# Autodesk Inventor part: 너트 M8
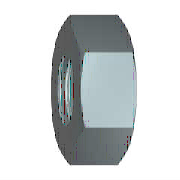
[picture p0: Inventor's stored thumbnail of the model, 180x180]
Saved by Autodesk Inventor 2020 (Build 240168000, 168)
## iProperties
Created: 2012-02
Part Number: 너트 M8
Material: 강철, 연강
Description: 6각 너트 및 6각 가는 너트
Document SubType Name: Modeling
Standard: KS B 1012
Designer: mduedu
Standards Organization: KS
Language: ko-KR
Size Designation: M 8
Categories: <MemberInstance><Categories><Category DisplayName="조임쇠" InternalName="e4da775c-781d-43d5-af7c-5136215cf5a6" Mnemonic="FSTN"><Category DisplayName="너트" InternalN
Density: 7.86 g/cm^3
Mass: 4.30432 g
Surface Area: 5.27675 cm^2
Volume: 0.547623 cm^3
Appearance: 강철
IsCustomPart: 1
Author: mduedu
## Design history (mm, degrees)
sketch "스케치1"
  geometry: L1 (-7.506, 0)-(-3.753, 6.5); L2 (-3.753, 6.5)-(3.753, 6.5); L3 (3.753, 6.5)-(7.506, 0); L4 (7.506, 0)-(3.753, -6.5); L5 (3.753, -6.5)-(-3.753, -6.5); L6 (-3.753, -6.5)-(-7.506, 0); 2 further points
  constraints: 12 end point, 1 coincident, 1 horizontal, 11 other
  dimensions: "d0" = 15.01111 distance of L3.end L1.start (= 1.1547 x SW)
extrude "본체" new body sketch "스케치1" distance "d1" = 5 (= KOH); taper "d2" = 0 deg
sketch "스케치2"
  geometry: L1 (0, 3.753)-(0, 7.506) reference; L2 (0, 7.506)-(5, 7.506) reference; L3 (5, 3.753)-(5, 7.506) reference; L4 (-1, 0)-(6, 0) reference; L5 (0.581, 7.506)-(0, 6.5); L6 (4.419, 7.506)-(5, 6.5)
  constraints: 4 end point, 4 point on line
  dimensions: "d3" = 30 deg angle of L1 L5 (= ANG1); "d4" = 30 deg angle of L3 L6 (= ANG2); "d5" = 13 diameter of L5.end L4 (= SW0); "d6" = 13 diameter of L6.end L4 (= SW01)
revolve "모따기1" sketch "스케치2" stored, may be unused: angle "d7" = 90 deg
sketch "스케치3"
  geometry: A1 r 6.5 centre (0, 0) between (-3.25, -5.629) and (3.25, -5.629) reference; 1 further point
  constraints: 1 coincident
hole "스레드" sketch "스케치3" at (0, 0) diameter "d25" = 6.647; stored, may be unused: countersink angle "d29" = 82 deg, drill point angle "d31" = 118 deg; dims "d26" = 6, "d27" = 4, "d28" = 2, "d30" = 8
workaxis "Work Axis1"
workplane "Work Plane1"
body "Solid1"
chamfer "모따기2" distance "d8" = 0.67658 (= -0.5 x GD1 + 0.5 x NND); stored, may be unused: angle "d9" = 30 deg, second distance "d40" = 0.67658 (= -0.5 x GD1 + 0.5 x NND)
chamfer "모따기3" distance "d10" = 0.67658 (= -0.5 x GD1 + 0.5 x NND); stored, may be unused: angle "d11" = 30 deg, second distance "d41" = 0.67658 (= -0.5 x GD1 + 0.5 x NND)
other parameters: "ANG1" = 30 deg [user parameter; used in 1 equation term], "ANG2" = 30 deg [user parameter; used in 1 equation term], "NND" = 8 [user parameter; used in 4 equation terms], "KOH" = 5 [user parameter; used in 1 equation term], "SW" = 13 [user parameter; used in 4 equation terms], "SW0" = 13 (= SW) [user parameter; used in 1 equation term], "SW01" = 13 (= SW) [user parameter; used in 1 equation term], "GD1" = 6.64684 (computed from THREADDIA, PTC, TOA) [user parameter; used in 4 equation terms], "d13" = 0, "d14" = 0, "d39" = 0, "d42" = 0, "GUL" = 0.67658 (= 0.541266 x PTC) [user parameter], "TPU" = 8 (computed from PTC) [user parameter], "THREADDIA" = 8 [user parameter; used in 1 equation term], "TOA" = 30 deg [user parameter; used in 1 equation term], "PTC" = 1.25 [user parameter; used in 4 equation terms], "E0" = 15.015 (= 1.155 x SW) [user parameter], "GAL" = 0.67658 (= 0.541266 x PTC) [user parameter]
